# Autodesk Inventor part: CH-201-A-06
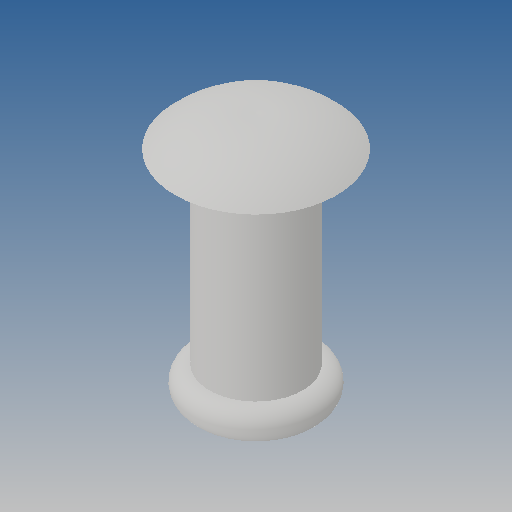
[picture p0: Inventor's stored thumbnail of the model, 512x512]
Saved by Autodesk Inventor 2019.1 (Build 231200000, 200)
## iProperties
Created: 2012-09
Part Number: CH-201-A-06
Material: Ogólny
Document SubType Name: Modeling
Designer: CADENGINEERING4
Density: 1 g/cm^3
Appearance: Domyślna
Author: CADENGINEERING4
Revision Number: ÈÎºÎ
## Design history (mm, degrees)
feature "Ô²½Ç2"
node "Bryła1"
